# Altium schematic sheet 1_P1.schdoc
size 307 x 218 mm; Symbol: Drawing-Symbol_A4; Device: Drawing-Symbol_A4; @Project Name: Cockroft_Walton_Adjustable; @Page Count: 1; @Update Date: 2025-01-03; @Create Date: 2025-01-03; @Schematic Name: Schematic1; @Page No: 1; @Page Name: P1; Company: EasyEDA.com; Version: V1.0; Page Size: A4; @Create Time: 06:54:10; @Update Time: 09:54:10; Width: 1170; Height: 825; Region Start: 1; X Region Count: 6; Y Region Count: 4; Blade Width: 10; Title Block Position: 3; @Board Name: Board1
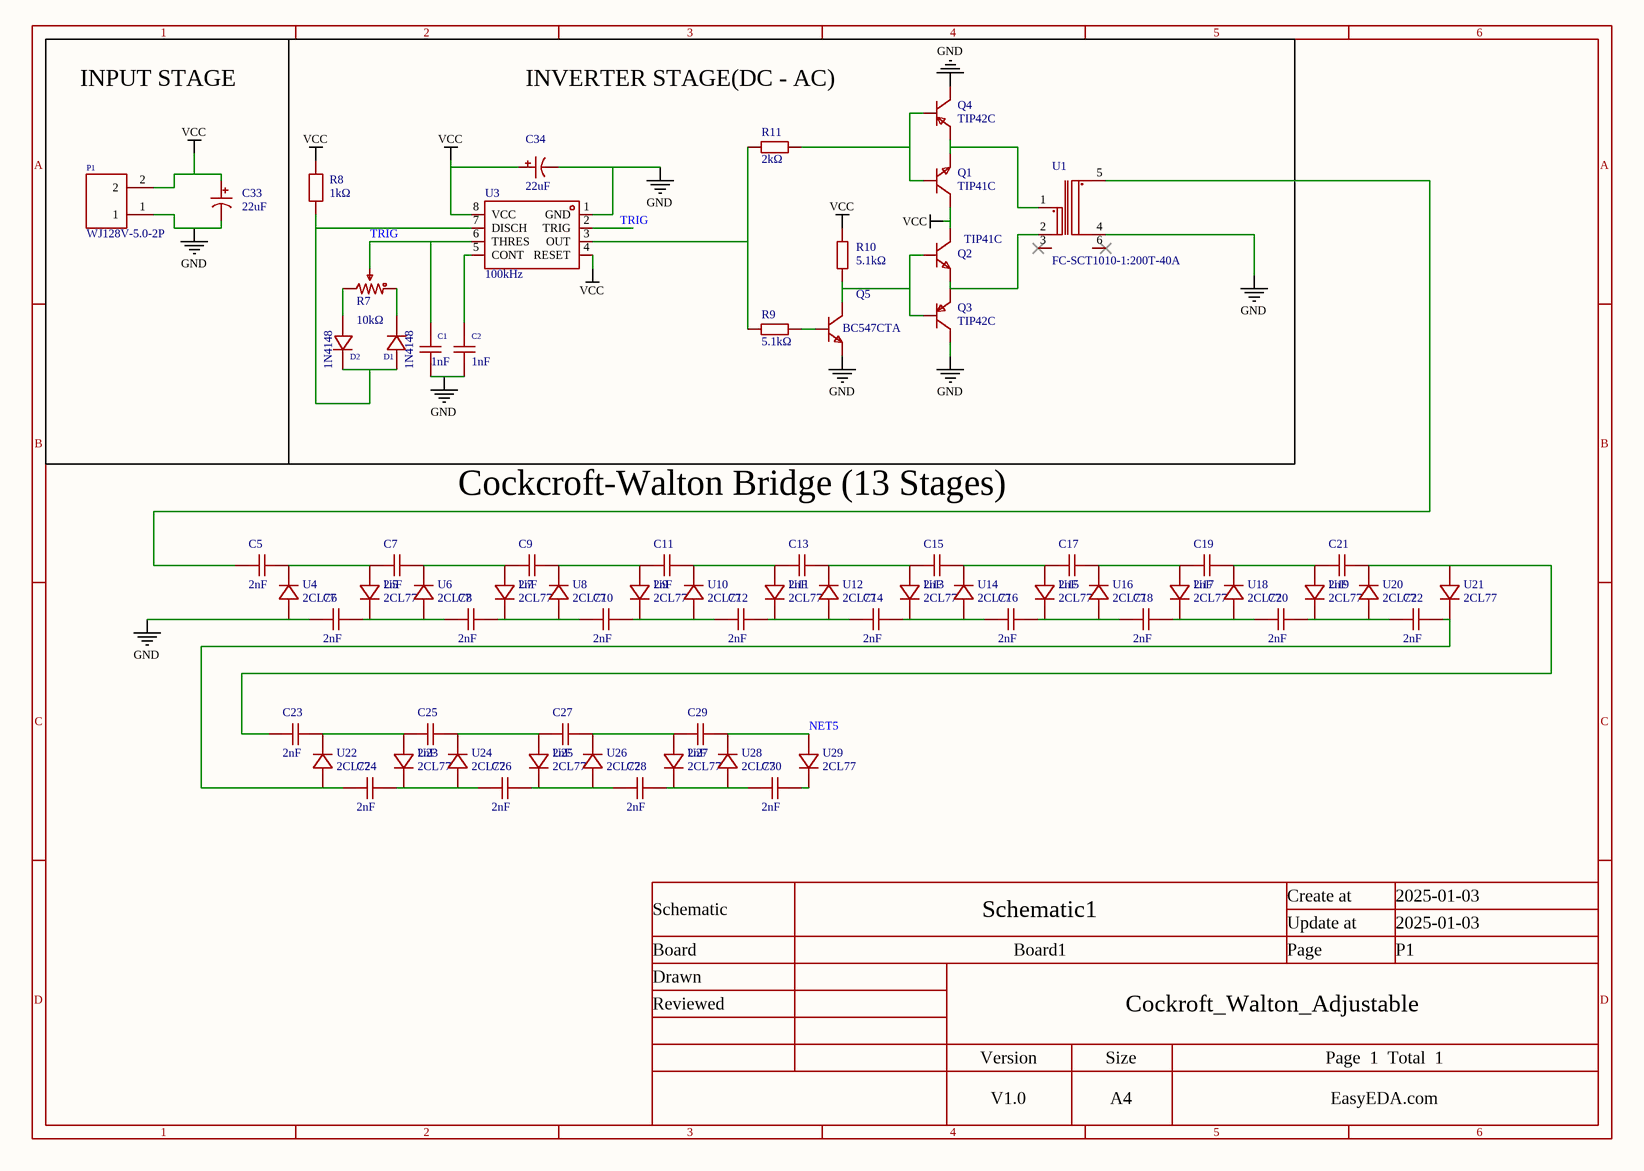
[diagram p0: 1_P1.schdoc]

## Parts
C1  1nF  [CAP-TH_L8.0-W3.0-P5.0-D0.60]
C2  1nF  [CAP-TH_L8.0-W3.0-P5.0-D0.60]
C5  2nF  [CAP-TH_L19.0-W8.0-P12.50-D0.8-S8.0]
C6  2nF  [CAP-TH_L19.0-W8.0-P12.50-D0.8-S8.0]
C7  2nF  [CAP-TH_L19.0-W8.0-P12.50-D0.8-S8.0]
C8  2nF  [CAP-TH_L19.0-W8.0-P12.50-D0.8-S8.0]
C9  2nF  [CAP-TH_L19.0-W8.0-P12.50-D0.8-S8.0]
C10  2nF  [CAP-TH_L19.0-W8.0-P12.50-D0.8-S8.0]
C11  2nF  [CAP-TH_L19.0-W8.0-P12.50-D0.8-S8.0]
C12  2nF  [CAP-TH_L19.0-W8.0-P12.50-D0.8-S8.0]
C13  2nF  [CAP-TH_L19.0-W8.0-P12.50-D0.8-S8.0]
C14  2nF  [CAP-TH_L19.0-W8.0-P12.50-D0.8-S8.0]
C15  2nF  [CAP-TH_L19.0-W8.0-P12.50-D0.8-S8.0]
C16  2nF  [CAP-TH_L19.0-W8.0-P12.50-D0.8-S8.0]
C17  2nF  [CAP-TH_L19.0-W8.0-P12.50-D0.8-S8.0]
C18  2nF  [CAP-TH_L19.0-W8.0-P12.50-D0.8-S8.0]
C19  2nF  [CAP-TH_L19.0-W8.0-P12.50-D0.8-S8.0]
C20  2nF  [CAP-TH_L19.0-W8.0-P12.50-D0.8-S8.0]
C21  2nF  [CAP-TH_L19.0-W8.0-P12.50-D0.8-S8.0]
C22  2nF  [CAP-TH_L19.0-W8.0-P12.50-D0.8-S8.0]
C23  2nF  [CAP-TH_L19.0-W8.0-P12.50-D0.8-S8.0]
C24  2nF  [CAP-TH_L19.0-W8.0-P12.50-D0.8-S8.0]
C25  2nF  [CAP-TH_L19.0-W8.0-P12.50-D0.8-S8.0]
C26  2nF  [CAP-TH_L19.0-W8.0-P12.50-D0.8-S8.0]
C27  2nF  [CAP-TH_L19.0-W8.0-P12.50-D0.8-S8.0]
C28  2nF  [CAP-TH_L19.0-W8.0-P12.50-D0.8-S8.0]
C29  2nF  [CAP-TH_L19.0-W8.0-P12.50-D0.8-S8.0]
C30  2nF  [CAP-TH_L19.0-W8.0-P12.50-D0.8-S8.0]
C33  22uF  [CAP-TH_BD5.0-P2.00-D0.8-FD]
C34  22uF  [CAP-TH_BD5.0-P2.00-D0.8-FD]
D1  1N4148  [DO-35_BD2.0-L4.2-P8.20-D0.5-RD]
D2  1N4148  [DO-35_BD2.0-L4.2-P8.20-D0.5-RD]
P1  WJ128V-5.0-2P  [CONN-TH_2P-P5.00_WJ128V-5.0-2P]
Q1  TIP41C  [TO-220-3_L10.0-W4.5-P2.54-T]
Q2  TIP41C  [TO-220-3_L10.0-W4.5-P2.54-T]
Q3  TIP42C  [ITO-220AB-3_L10.2-W4.5-P2.60-L]
Q4  TIP42C  [ITO-220AB-3_L10.2-W4.5-P2.60-L]
Q5  BC547CTA  [TO-92-3_L4.8-W3.7-P2.54-L]
R7  10kΩ  [RES-ADJ-TH_3P-L10.0-W10.0-P2.50-L]
R8  1kΩ  [RES-TH_BD2.3-L6.5-P10.50-D0.5]
R9  5.1kΩ  [RES-TH_BD2.2-L6.5-P10.50-D0.6]
R10  5.1kΩ  [RES-TH_BD2.2-L6.5-P10.50-D0.6]
R11  2kΩ  [RES-TH_BD2.2-L6.5-P10.50-D0.6]
U1  FC-SCT1010-1:200T-40A  [XFMR-SMD_6P-P2.50_FC-SCT1010]
U3  100kHz  [DIP-8_L9.8-W6.6-P2.54-LS7.6-BL]
U4  2CL77  [DIO-TH_BD3.0-L12.0-P16.00-D0.6]
U5  2CL77  [DIO-TH_BD3.0-L12.0-P16.00-D0.6]
U6  2CL77  [DIO-TH_BD3.0-L12.0-P16.00-D0.6]
U7  2CL77  [DIO-TH_BD3.0-L12.0-P16.00-D0.6]
U8  2CL77  [DIO-TH_BD3.0-L12.0-P16.00-D0.6]
U9  2CL77  [DIO-TH_BD3.0-L12.0-P16.00-D0.6]
U10  2CL77  [DIO-TH_BD3.0-L12.0-P16.00-D0.6]
U11  2CL77  [DIO-TH_BD3.0-L12.0-P16.00-D0.6]
U12  2CL77  [DIO-TH_BD3.0-L12.0-P16.00-D0.6]
U13  2CL77  [DIO-TH_BD3.0-L12.0-P16.00-D0.6]
U14  2CL77  [DIO-TH_BD3.0-L12.0-P16.00-D0.6]
U15  2CL77  [DIO-TH_BD3.0-L12.0-P16.00-D0.6]
U16  2CL77  [DIO-TH_BD3.0-L12.0-P16.00-D0.6]
U17  2CL77  [DIO-TH_BD3.0-L12.0-P16.00-D0.6]
U18  2CL77  [DIO-TH_BD3.0-L12.0-P16.00-D0.6]
U19  2CL77  [DIO-TH_BD3.0-L12.0-P16.00-D0.6]
U20  2CL77  [DIO-TH_BD3.0-L12.0-P16.00-D0.6]
U21  2CL77  [DIO-TH_BD3.0-L12.0-P16.00-D0.6]
U22  2CL77  [DIO-TH_BD3.0-L12.0-P16.00-D0.6]
U23  2CL77  [DIO-TH_BD3.0-L12.0-P16.00-D0.6]
U24  2CL77  [DIO-TH_BD3.0-L12.0-P16.00-D0.6]
U25  2CL77  [DIO-TH_BD3.0-L12.0-P16.00-D0.6]
U26  2CL77  [DIO-TH_BD3.0-L12.0-P16.00-D0.6]
U27  2CL77  [DIO-TH_BD3.0-L12.0-P16.00-D0.6]
U28  2CL77  [DIO-TH_BD3.0-L12.0-P16.00-D0.6]
U29  2CL77  [DIO-TH_BD3.0-L12.0-P16.00-D0.6]

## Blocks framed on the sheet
INPUT STAGE: C33 P1
INVERTER STAGE(DC - AC): C1 C2 C34 D1 D2 Q1-Q5 R7-R11 U1 U3

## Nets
GND: C1.1 C2.1 C6.1 C33.2 C34.2 P1.1 Q3.2(C) Q4.2(C) Q5.3(E) U1.4 U3.1(GND) U4.2(A)
VCC: C33.1 C34.1 P1.2 Q1.2(C) Q2.2(C) R8.2 R10.2 U3.4(RESET) U3.8(VCC)
NET5: C29.2 U28.1(K) U29.2(A)
TRIG: C1.2 R7.2 U3.2(TRIG) U3.6(THRES)
NetC2_2: C2.2 U3.5(CONT)
NetC5_1: C5.1 U1.5
NetC5_2: C5.2 C7.1 U4.1(K) U5.2(A)
NetC6_2: C6.2 C8.1 U5.1(K) U6.2(A)
NetC7_2: C7.2 C9.1 U6.1(K) U7.2(A)
NetC8_2: C8.2 C10.1 U7.1(K) U8.2(A)
NetC9_2: C9.2 C11.1 U8.1(K) U9.2(A)
NetC10_2: C10.2 C12.1 U9.1(K) U10.2(A)
NetC11_2: C11.2 C13.1 U10.1(K) U11.2(A)
NetC12_2: C12.2 C14.1 U11.1(K) U12.2(A)
NetC13_2: C13.2 C15.1 U12.1(K) U13.2(A)
NetC14_2: C14.2 C16.1 U13.1(K) U14.2(A)
NetC15_2: C15.2 C17.1 U14.1(K) U15.2(A)
NetC16_2: C16.2 C18.1 U15.1(K) U16.2(A)
NetC17_2: C17.2 C19.1 U16.1(K) U17.2(A)
NetC18_2: C18.2 C20.1 U17.1(K) U18.2(A)
NetC19_2: C19.2 C21.1 U18.1(K) U19.2(A)
NetC20_2: C20.2 C22.1 U19.1(K) U20.2(A)
NetC21_2: C21.2 C23.1 U20.1(K) U21.2(A)
NetC22_2: C22.2 C24.1 U21.1(K) U22.2(A)
NetC23_2: C23.2 C25.1 U22.1(K) U23.2(A)
NetC24_2: C24.2 C26.1 U23.1(K) U24.2(A)
NetC25_2: C25.2 C27.1 U24.1(K) U25.2(A)
NetC26_2: C26.2 C28.1 U25.1(K) U26.2(A)
NetC27_2: C27.2 C29.1 U26.1(K) U27.2(A)
NetC28_2: C28.2 C30.1 U27.1(K) U28.2(A)
NetC30_2: C30.2 U29.1(K)
NetD1_1: D1.1(C) R7.1
NetD1_2: D1.2(A) D2.1(C) R8.1 U3.7(DISCH)
NetD2_2: D2.2(A) R7.3
NetQ1_1: Q1.1(B) Q4.1(B) R11.2
NetQ1_3: Q1.3(E) Q4.3(E) U1.1
NetQ2_1: Q2.1(B) Q3.1(B) Q5.1(C) R10.1
NetQ2_3: Q2.3(E) Q3.3(E) U1.2
NetQ5_2: Q5.2(B) R9.2
NetR9_1: R9.1 R11.1 U3.3(OUT)

Not connected (* = marked no-connect by the designer): U1 3* 6*

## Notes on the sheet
- Cockcroft-Walton Bridge (13 Stages)

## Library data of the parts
C1 C2 = R08B1B102KN0B0S0N0: Manufacturer: STE(松田); Add into BOM: yes; Tolerance: ±10%
C5-C30 = HVCC153Y6P202MEAX: Manufacturer: VISHAY(威世); Add into BOM: yes; Tolerance: ±20%
C33 C34 = GR226M050D11RR0VH4FP0: Manufacturer: CX(承兴); Symbol: 22UF 50V高频低阻; Add into BOM: yes; Tolerance: ±20%; Lifetime @ Temp: 2000hrs@105℃
D1 D2 = 1N4148_C402212: Manufacturer: LGE(鲁光); Add into BOM: yes; Forward Voltage (Vf@If): 1V@10mA; Reverse Leakage Current: 5uA@75V
P1 = WJ128V-5.0-2P: Manufacturer: KANGNEX(康奈克斯电气); Add into BOM: yes; Structure: 1x2P; Pitch: 5mm; Current Rating (Max): 20A; Voltage Rating (Max): 250V; Wire Gauge - AWG: 12~22; Wire Gauge - mm2: 2.5; Number of PINs Per Row: 2
Q1 Q2 = TIP41C_C92310: Manufacturer: CJ(江苏长电/长晶); Add into BOM: yes; DC Current Gain (hFE@Ic,Vce): 15@3A,4V; Transition Frequency (fT): 3MHz; Collector Cut-Off Current (Icbo): 400uA; Collector-Emitter Saturation Voltage (VCE(sat)@Ic,Ib): 1.5V@6A,0.6A
Q3 Q4 = TIP42C_C410524: Manufacturer: ST(意法半导体); Add into BOM: yes; DC Current Gain (hFE@Ic,Vce): 15@6A,4V; Collector Cut-Off Current (Icbo): 0.7mA; Collector-Emitter Saturation Voltage (VCE(sat)@Ic,Ib): 1.5V@6A,0.6A
Q5 = BC547CTA: Manufacturer: onsemi(安森美); Add into BOM: yes; DC Current Gain (hFE@Ic,Vce): 110@2mA,5V; Transition Frequency (fT): 300MHz; Collector Cut-Off Current (Icbo): 15nA; Collector-Emitter Saturation Voltage (VCE(sat)@Ic,Ib): 250mV@100mA,5mA
R7 = 3296W-1-103_C118954: Manufacturer: BOCHEN(博晨); Add into BOM: yes; Tolerance: ±10%
R8 = MF1/4W-1KΩ±1%T52: Manufacturer: 华星机电; Add into BOM: yes; Tolerance: ±1%; Power(Watts): 250mW; Temperature Coefficient: ±200ppm/℃
R9 R10 = CFR0W4J0512A50: Manufacturer: UNI-ROYAL(厚声); Add into BOM: yes; Tolerance: ±5%; Overload Voltage (Max): 250V; Power(Watts): 250mW; Temperature Coefficient: ±450ppm/℃
R11 = MFR0W4F2001A50: Manufacturer: UNI-ROYAL(厚声); Add into BOM: yes; Tolerance: ±1%; Overload Voltage (Max): 250V; Power(Watts): 250mW; Temperature Coefficient: ±50ppm/℃
U1 = FC-SCT1010-1:200T-40A: Manufacturer: FC(方成); Add into BOM: yes; Current Ratio: 1:200; Current Rating: 40A
U3 = NE555P: Manufacturer: TI(德州仪器); Add into BOM: yes; Supply Voltage: 4.5V~16V; Supply Current: 10mA
U4-U29 = 2CL77: Manufacturer: SUNMATE(森美特); Add into BOM: yes; Reverse Leakage Current: 2uA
